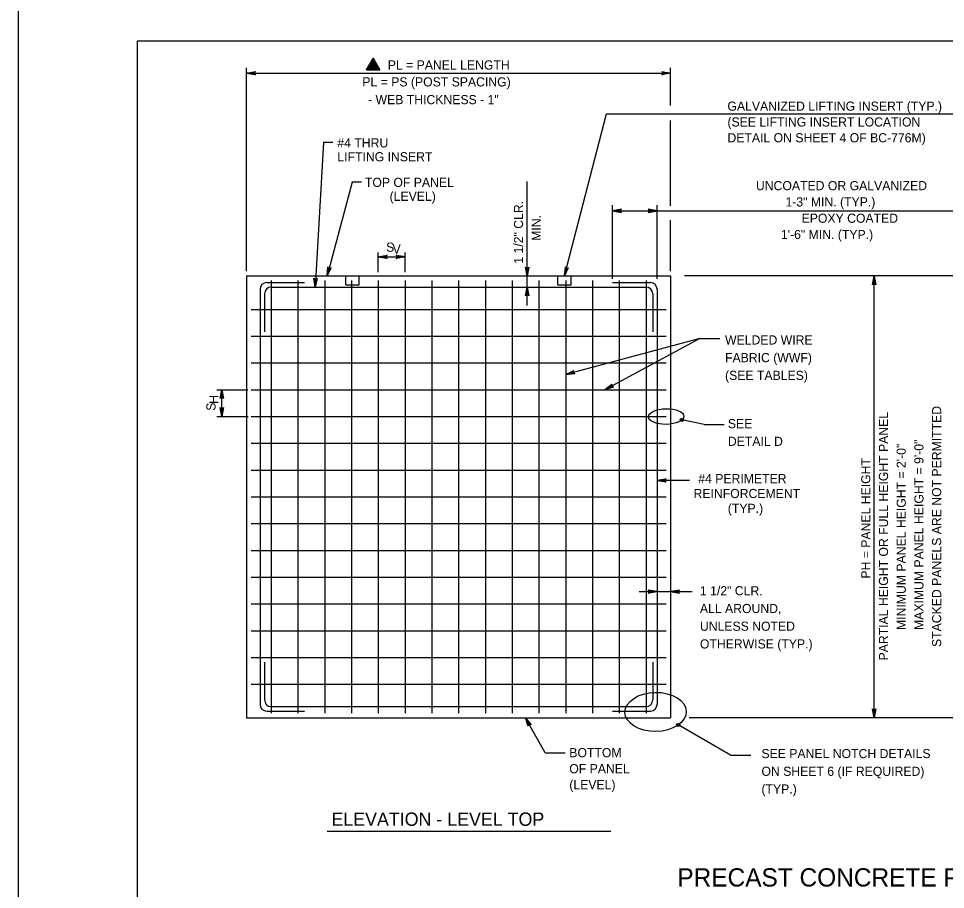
# Model space of a CAD drawing. Extents: x 3761 to 5458, y -616 to 1166.
# Drawn here: x 3761.3 to 4072.9, y -322.5 to -29.8 of the extents above; entities that cross this region are included whole.
import ezdxf

# ---------------------------------------------------------------- set-up
doc = ezdxf.new("R2010")
doc.units = 0
for name, color, linetype in [('1', 7, 'Continuous'), ('2', 7, 'Continuous'), ('PLT-BNDY', 7, 'Continuous')]:
    doc.layers.add(name, color=color, linetype=linetype)

msp = doc.modelspace()

# ---------------------------------------------------------------- linework, layer by layer
at = {"layer": '1'}
for p, q in [((3838.02, -114.74), (3838.02, -46.32)), ((3880.52, -45.74), (3880.52, -45.74)), ((3980.52, -59.07), (3980.52, -46.32)), ((3838.02, -48.22), (3980.52, -48.22)), ((3944.89, -116.32), (3958.96, -61.84)), ((3958.96, -61.84), (4133.46, -61.84)), ((3980.52, -92.71), (3980.52, -64.09)), ((3863.87, -71.45), (3861.01, -120.07)), ((3867.01, -71.45), (3863.87, -71.45)), ((3873.53, -84.81), (3865.1, -116.32)), ((3876.67, -84.81), (3873.53, -84.81)), ((3932.35, -126.29), (3932.35, -84.55)), ((3961.02, -117.3), (3961.02, -92.48)), ((3976.02, -117.3), (3976.02, -92.48)), ((3961.02, -94.44), (4107.86, -94.44)), ((3980.52, -114.74), (3980.52, -97.6)), ((3882.27, -115.01), (3882.27, -108.43)), ((3891.27, -115.01), (3891.27, -108.43)), ((3882.27, -109.9), (3891.27, -109.9)), ((3838.02, -116.32), (3838.02, -264.82)), ((3838.02, -116.32), (3980.52, -116.32)), ((3846.27, -117.82), (3846.27, -263.33)), ((3855.27, -117.82), (3855.27, -263.33)), ((3864.27, -117.82), (3864.27, -263.33)), ((3871.39, -119.32), (3871.39, -116.32)), ((3873.27, -117.82), (3873.27, -263.33)), ((3875.89, -119.32), (3875.89, -116.32)), ((3882.27, -117.82), (3882.27, -263.33)), ((3891.27, -117.82), (3891.27, -263.33)), ((3900.27, -117.82), (3900.27, -263.33)), ((3909.27, -117.82), (3909.27, -263.33)), ((3918.27, -117.82), (3918.27, -263.33)), ((3927.27, -117.82), (3927.27, -263.33)), ((3936.27, -117.82), (3936.27, -263.33)), ((3942.64, -119.32), (3942.64, -116.32)), ((3945.27, -117.82), (3945.27, -263.33)), ((3947.14, -119.32), (3947.14, -116.32)), ((3954.27, -117.82), (3954.27, -263.33)), ((3963.27, -117.82), (3963.27, -263.33)), ((3972.27, -117.82), (3972.27, -263.33)), ((3980.52, -116.32), (3980.52, -264.82)), ((4112.25, -116.32), (3985.19, -116.32)), ((4048.91, -264.82), (4048.91, -116.32)), ((3842.52, -120.82), (3842.52, -260.32)), ((3844.77, -118.57), (3857.52, -118.57)), ((3846.27, -120.07), (3972.27, -120.07)), ((3871.39, -119.32), (3875.89, -119.32)), ((3942.64, -119.32), (3947.14, -119.32)), ((3961.02, -118.57), (3973.77, -118.57)), ((3976.02, -120.82), (3976.02, -260.32)), ((3844.02, -122.32), (3844.02, -135.07)), ((3974.52, -122.32), (3974.52, -135.07)), ((3839.52, -127.57), (3979.02, -127.57)), ((3839.52, -136.57), (3979.02, -136.57)), ((3990.33, -137.36), (3945.27, -149.41)), ((3990.33, -137.36), (3958.44, -154.57)), ((3990.33, -137.36), (3997.07, -137.36)), ((3839.52, -145.57), (3979.02, -145.57)), ((3827.99, -154.57), (3838.42, -154.57)), ((3829.63, -163.57), (3829.63, -154.57)), ((3839.52, -154.57), (3979.02, -154.57)), ((3827.99, -163.57), (3838.51, -163.57)), ((3839.52, -163.57), (3979.02, -163.57)), ((3991.79, -166.23), (3984.3, -164.72)), ((3991.79, -166.23), (3998.52, -166.23)), ((3839.52, -172.57), (3979.02, -172.57)), ((3839.52, -181.57), (3979.02, -181.57)), ((3986.87, -185.05), (3976.02, -185.05)), ((3839.52, -190.57), (3979.02, -190.57)), ((3839.52, -199.57), (3979.02, -199.57)), ((3839.52, -208.57), (3979.02, -208.57)), ((3839.52, -217.57), (3979.02, -217.57)), ((3970, -222.43), (3987.73, -222.43)), ((3839.52, -226.57), (3979.02, -226.57)), ((3839.52, -235.57), (3979.02, -235.57)), ((3839.52, -244.57), (3979.02, -244.57)), ((3844.02, -246.08), (3844.02, -258.83)), ((3974.52, -246.08), (3974.52, -258.83)), ((3839.52, -253.57), (3979.02, -253.57)), ((3846.27, -261.08), (3972.27, -261.08)), ((3838.02, -264.82), (3980.52, -264.82)), ((3844.77, -262.57), (3857.52, -262.57)), ((3938.33, -276.61), (3931.72, -264.82)), ((3961.02, -262.57), (3973.77, -262.57)), ((4110.98, -264.82), (3986.76, -264.82)), ((4000.72, -277.4), (3983.09, -267.24)), ((3938.33, -276.61), (3945.06, -276.61)), ((4000.72, -277.4), (4007.45, -277.4)), ((3865.09, -302.99), (3960.49, -302.99))]:
    msp.add_line(p, q, dxfattribs=at)
for points in [[(3878.29, -47.03), (3882.75, -47.03), (3880.52, -43.17), (3878.29, -47.03)], [(3878.29, -47.03), (3880.52, -43.17), (3882.75, -47.03), (3878.29, -47.03), (3880.51, -43.28), (3882.68, -46.98), (3878.37, -46.99), (3880.52, -43.39), (3882.59, -46.92), (3878.48, -46.94), (3880.52, -43.51), (3882.49, -46.85), (3878.57, -46.88), (3880.52, -43.62), (3882.39, -46.8), (3878.68, -46.81), (3880.52, -43.76), (3882.28, -46.75), (3878.8, -46.75), (3880.52, -43.9), (3882.18, -46.68), (3878.9, -46.69), (3880.51, -44.03), (3882.07, -46.61), (3879.01, -46.62), (3880.51, -44.16), (3881.95, -46.54), (3879.12, -46.56), (3880.53, -44.28), (3881.81, -46.48), (3879.23, -46.5), (3880.53, -44.41), (3881.68, -46.4), (3879.35, -46.44), (3880.53, -44.56), (3881.56, -46.32), (3879.47, -46.37), (3880.52, -44.69), (3881.44, -46.25), (3879.6, -46.3), (3880.53, -44.82), (3881.33, -46.19), (3879.73, -46.24), (3880.52, -44.97), (3881.2, -46.12), (3879.87, -46.17), (3880.52, -45.1), (3881.06, -46.04), (3879.98, -46.11), (3880.52, -45.23), (3880.94, -45.97), (3880.1, -46.05), (3880.52, -45.36), (3880.83, -45.93), (3880.21, -45.99), (3880.52, -45.48), (3880.74, -45.87), (3880.31, -45.93), (3880.52, -45.61), (3880.65, -45.82), (3880.43, -45.85), (3880.52, -45.75), (3882.74, -47.02), (3880.52, -45.75), (3880.52, -43.19), (3880.52, -45.76), (3878.29, -47.02)], [(3838.02, -48.22), (3841, -47.66), (3840.77, -47.82), (3840.65, -48.02), (3840.62, -48.22), (3840.65, -48.42), (3840.77, -48.62), (3841, -48.78), (3838.02, -48.22), (3840.77, -48.62), (3840.65, -48.42), (3838.02, -48.22), (3840.62, -48.22), (3840.65, -48.02), (3838.02, -48.22), (3840.77, -47.82)], [(3980.52, -48.22), (3977.54, -48.78), (3977.77, -48.62), (3977.88, -48.42), (3977.92, -48.22), (3977.88, -48.02), (3977.77, -47.82), (3977.54, -47.66), (3980.52, -48.22), (3977.77, -47.82), (3977.88, -48.02), (3980.52, -48.22), (3977.92, -48.22), (3977.88, -48.42), (3980.52, -48.22), (3977.77, -48.62)], [(3961.02, -94.44), (3964, -95), (3963.89, -94.92), (3963.77, -94.84), (3963.71, -94.74), (3963.65, -94.64), (3963.64, -94.54), (3963.62, -94.44), (3963.64, -94.34), (3963.65, -94.24), (3963.71, -94.14), (3963.77, -94.04), (3963.89, -93.96), (3964, -93.88), (3961.02, -94.44), (3963.89, -93.96), (3963.77, -94.04), (3961.02, -94.44), (3963.71, -94.14), (3963.65, -94.24), (3961.02, -94.44), (3963.64, -94.34), (3963.62, -94.44), (3961.02, -94.44), (3963.64, -94.54), (3963.65, -94.64), (3961.02, -94.44), (3963.71, -94.74), (3963.77, -94.84), (3961.02, -94.44), (3963.89, -94.92)], [(3976.02, -94.44), (3973.04, -93.88), (3973.15, -93.96), (3973.27, -94.04), (3973.32, -94.14), (3973.38, -94.24), (3973.4, -94.34), (3973.42, -94.44), (3973.4, -94.54), (3973.38, -94.64), (3973.32, -94.74), (3973.27, -94.84), (3973.15, -94.92), (3973.04, -95), (3976.02, -94.44), (3973.15, -94.92), (3973.27, -94.84), (3976.02, -94.44), (3973.32, -94.74), (3973.38, -94.64), (3976.02, -94.44), (3973.4, -94.54), (3973.42, -94.44), (3976.02, -94.44), (3973.4, -94.34), (3973.38, -94.24), (3976.02, -94.44), (3973.32, -94.14), (3973.27, -94.04), (3976.02, -94.44), (3973.15, -93.96)], [(3882.27, -109.9), (3885.25, -109.34), (3885.02, -109.5), (3884.9, -109.7), (3884.87, -109.9), (3884.9, -110.1), (3885.02, -110.3), (3885.25, -110.46), (3882.27, -109.9), (3885.02, -110.3), (3884.9, -110.1), (3882.27, -109.9), (3884.87, -109.9), (3884.9, -109.7), (3882.27, -109.9), (3885.02, -109.5)], [(3891.27, -109.9), (3888.28, -110.46), (3888.51, -110.3), (3888.63, -110.1), (3888.67, -109.9), (3888.63, -109.7), (3888.51, -109.5), (3888.28, -109.34), (3891.27, -109.9), (3888.51, -109.5), (3888.63, -109.7), (3891.27, -109.9), (3888.67, -109.9), (3888.63, -110.1), (3891.27, -109.9), (3888.51, -110.3)], [(3865.1, -116.32), (3865.33, -113.3), (3865.38, -113.43), (3865.43, -113.56), (3865.51, -113.65), (3865.59, -113.73), (3865.68, -113.77), (3865.77, -113.81), (3865.88, -113.82), (3865.98, -113.83), (3866.09, -113.8), (3866.2, -113.77), (3866.31, -113.68), (3866.41, -113.59), (3865.1, -116.32), (3866.31, -113.68), (3866.2, -113.77), (3865.1, -116.32), (3866.09, -113.8), (3865.98, -113.83), (3865.1, -116.32), (3865.88, -113.82), (3865.77, -113.81), (3865.1, -116.32), (3865.68, -113.77), (3865.59, -113.73), (3865.1, -116.32), (3865.51, -113.65), (3865.43, -113.56), (3865.1, -116.32), (3865.38, -113.43)], [(3932.35, -116.32), (3931.79, -113.34), (3931.95, -113.57), (3932.15, -113.69), (3932.35, -113.72), (3932.55, -113.69), (3932.75, -113.57), (3932.91, -113.34), (3932.35, -116.32), (3932.75, -113.57), (3932.55, -113.69), (3932.35, -116.32), (3932.35, -113.72), (3932.15, -113.69), (3932.35, -116.32), (3931.95, -113.57)], [(3944.89, -116.32), (3946.26, -113.62), (3946.15, -113.7), (3946.04, -113.79), (3945.93, -113.82), (3945.82, -113.85), (3945.72, -113.84), (3945.62, -113.83), (3945.53, -113.78), (3945.44, -113.74), (3945.36, -113.65), (3945.28, -113.57), (3945.23, -113.44), (3945.19, -113.3), (3944.89, -116.32), (3945.23, -113.44), (3945.28, -113.57), (3944.89, -116.32), (3945.36, -113.65), (3945.44, -113.74), (3944.89, -116.32), (3945.53, -113.78), (3945.62, -113.83), (3944.89, -116.32), (3945.72, -113.84), (3945.82, -113.85), (3944.89, -116.32), (3945.93, -113.82), (3946.04, -113.79), (3944.89, -116.32), (3946.15, -113.7)], [(3861.01, -120.07), (3860.63, -117.06), (3860.78, -117.3), (3860.97, -117.43), (3861.17, -117.48), (3861.37, -117.46), (3861.57, -117.35), (3861.75, -117.13), (3861.01, -120.07), (3861.57, -117.35), (3861.37, -117.46), (3861.01, -120.07), (3861.17, -117.48), (3860.97, -117.43), (3861.01, -120.07), (3860.78, -117.3)], [(4048.91, -116.32), (4049.47, -119.31), (4049.39, -119.19), (4049.31, -119.08), (4049.21, -119.02), (4049.11, -118.96), (4049.01, -118.94), (4048.91, -118.92), (4048.81, -118.94), (4048.71, -118.96), (4048.61, -119.02), (4048.51, -119.08), (4048.43, -119.19), (4048.35, -119.31), (4048.91, -116.32), (4048.43, -119.19), (4048.51, -119.08), (4048.91, -116.32), (4048.61, -119.02), (4048.71, -118.96), (4048.91, -116.32), (4048.81, -118.94), (4048.91, -118.92), (4048.91, -116.32), (4049.01, -118.94), (4049.11, -118.96), (4048.91, -116.32), (4049.21, -119.02), (4049.31, -119.08), (4048.91, -116.32), (4049.39, -119.19)], [(3932.35, -120.07), (3932.91, -123.06), (3932.75, -122.83), (3932.55, -122.71), (3932.35, -122.67), (3932.15, -122.71), (3931.95, -122.83), (3931.79, -123.06), (3932.35, -120.07), (3931.95, -122.83), (3932.15, -122.71), (3932.35, -120.07), (3932.35, -122.67), (3932.55, -122.71), (3932.35, -120.07), (3932.75, -122.83)], [(3945.27, -149.41), (3948, -148.1), (3947.91, -148.2), (3947.82, -148.31), (3947.79, -148.42), (3947.76, -148.54), (3947.77, -148.64), (3947.78, -148.74), (3947.82, -148.83), (3947.86, -148.92), (3947.95, -149), (3948.03, -149.08), (3948.16, -149.13), (3948.29, -149.18), (3945.27, -149.41), (3948.16, -149.13), (3948.03, -149.08), (3945.27, -149.41), (3947.95, -149), (3947.86, -148.92), (3945.27, -149.41), (3947.82, -148.83), (3947.78, -148.74), (3945.27, -149.41), (3947.77, -148.64), (3947.76, -148.54), (3945.27, -149.41), (3947.79, -148.42), (3947.82, -148.31), (3945.27, -149.41), (3947.91, -148.2)], [(3958.44, -154.57), (3960.8, -152.67), (3960.73, -152.79), (3960.67, -152.92), (3960.67, -153.03), (3960.66, -153.15), (3960.69, -153.24), (3960.73, -153.34), (3960.79, -153.42), (3960.85, -153.5), (3960.95, -153.56), (3961.05, -153.62), (3961.19, -153.63), (3961.33, -153.65), (3958.44, -154.57), (3961.19, -153.63), (3961.05, -153.62), (3958.44, -154.57), (3960.95, -153.56), (3960.85, -153.5), (3958.44, -154.57), (3960.79, -153.42), (3960.73, -153.34), (3958.44, -154.57), (3960.69, -153.24), (3960.66, -153.15), (3958.44, -154.57), (3960.67, -153.03), (3960.67, -152.92), (3958.44, -154.57), (3960.73, -152.79)], [(3829.63, -154.57), (3830.19, -157.56), (3830.03, -157.33), (3829.83, -157.21), (3829.63, -157.17), (3829.43, -157.21), (3829.23, -157.33), (3829.07, -157.56), (3829.63, -154.57), (3829.23, -157.33), (3829.43, -157.21), (3829.63, -154.57), (3829.63, -157.17), (3829.83, -157.21), (3829.63, -154.57), (3830.03, -157.33)], [(3829.63, -163.57), (3829.07, -160.59), (3829.23, -160.82), (3829.43, -160.94), (3829.63, -160.97), (3829.83, -160.94), (3830.03, -160.82), (3830.19, -160.59), (3829.63, -163.57), (3830.03, -160.82), (3829.83, -160.94), (3829.63, -163.57), (3829.63, -160.97), (3829.43, -160.94), (3829.63, -163.57), (3829.23, -160.82)], [(3829.63, -163.57), (3829.07, -160.59), (3829.23, -160.82), (3829.43, -160.94), (3829.63, -160.97), (3829.83, -160.94), (3830.03, -160.82), (3830.19, -160.59), (3829.63, -163.57), (3830.03, -160.82), (3829.83, -160.94), (3829.63, -163.57), (3829.63, -160.97), (3829.43, -160.94), (3829.63, -163.57), (3829.23, -160.82)], [(3976.02, -185.05), (3979, -184.49), (3978.89, -184.57), (3978.77, -184.65), (3978.71, -184.75), (3978.65, -184.85), (3978.64, -184.95), (3978.62, -185.05), (3978.64, -185.15), (3978.65, -185.25), (3978.71, -185.35), (3978.77, -185.45), (3978.89, -185.53), (3979, -185.61), (3976.02, -185.05), (3978.89, -185.53), (3978.77, -185.45), (3976.02, -185.05), (3978.71, -185.35), (3978.65, -185.25), (3976.02, -185.05), (3978.64, -185.15), (3978.62, -185.05), (3976.02, -185.05), (3978.64, -184.95), (3978.65, -184.85), (3976.02, -185.05), (3978.71, -184.75), (3978.77, -184.65), (3976.02, -185.05), (3978.89, -184.57)], [(3976.02, -222.43), (3973.04, -222.99), (3973.15, -222.91), (3973.27, -222.83), (3973.32, -222.73), (3973.38, -222.63), (3973.4, -222.53), (3973.42, -222.43), (3973.4, -222.33), (3973.38, -222.23), (3973.32, -222.13), (3973.27, -222.03), (3973.15, -221.95), (3973.04, -221.87), (3976.02, -222.43), (3973.15, -221.95), (3973.27, -222.03), (3976.02, -222.43), (3973.32, -222.13), (3973.38, -222.23), (3976.02, -222.43), (3973.4, -222.33), (3973.42, -222.43), (3976.02, -222.43), (3973.4, -222.53), (3973.38, -222.63), (3976.02, -222.43), (3973.32, -222.73), (3973.27, -222.83), (3976.02, -222.43), (3973.15, -222.91)], [(3980.52, -222.43), (3983.5, -221.87), (3983.39, -221.95), (3983.27, -222.03), (3983.21, -222.13), (3983.15, -222.23), (3983.14, -222.33), (3983.12, -222.43), (3983.14, -222.53), (3983.15, -222.63), (3983.21, -222.73), (3983.27, -222.83), (3983.39, -222.91), (3983.5, -222.99), (3980.52, -222.43), (3983.39, -222.91), (3983.27, -222.83), (3980.52, -222.43), (3983.21, -222.73), (3983.15, -222.63), (3980.52, -222.43), (3983.14, -222.53), (3983.12, -222.43), (3980.52, -222.43), (3983.14, -222.33), (3983.15, -222.23), (3980.52, -222.43), (3983.21, -222.13), (3983.27, -222.03), (3980.52, -222.43), (3983.39, -221.95)], [(3931.72, -264.82), (3933.67, -267.15), (3933.41, -267.03), (3933.18, -267.02), (3932.99, -267.09), (3932.83, -267.22), (3932.72, -267.42), (3932.69, -267.7), (3931.72, -264.82), (3932.72, -267.42), (3932.83, -267.22), (3931.72, -264.82), (3932.99, -267.09), (3933.18, -267.02), (3931.72, -264.82), (3933.41, -267.03)], [(4048.91, -264.82), (4048.35, -261.84), (4048.43, -261.96), (4048.51, -262.07), (4048.61, -262.13), (4048.71, -262.19), (4048.81, -262.21), (4048.91, -262.22), (4049.01, -262.21), (4049.11, -262.19), (4049.21, -262.13), (4049.31, -262.07), (4049.39, -261.96), (4049.47, -261.84), (4048.91, -264.82), (4049.39, -261.96), (4049.31, -262.07), (4048.91, -264.82), (4049.21, -262.13), (4049.11, -262.19), (4048.91, -264.82), (4049.01, -262.21), (4048.91, -262.22), (4048.91, -264.82), (4048.81, -262.21), (4048.71, -262.19), (4048.91, -264.82), (4048.61, -262.13), (4048.51, -262.07), (4048.91, -264.82), (4048.43, -261.96)]]:
    msp.add_lwpolyline(points, dxfattribs=at)
for centre, radius in [((3984.3, -164.72), 0.533), ((3984.3, -164.72), 0.267), ((3983.09, -267.24), 0.533), ((3983.09, -267.24), 0.267)]:
    msp.add_circle(centre, radius, dxfattribs=at)
for centre, start, end in [((3844.77, -120.82), 90, 180), ((3846.27, -122.32), 90, 180), ((3972.27, -122.32), 0, 90), ((3973.77, -120.82), 0, 90), ((3844.77, -260.32), 180, 270), ((3846.27, -258.83), 180, 270), ((3972.27, -258.83), 270, 360), ((3973.77, -260.32), 270, 0)]:
    msp.add_arc(centre, 2.25, start, end, dxfattribs=at)
for centre, major_axis, ratio in [((3979.02, -163.57), (-5.94, -0.09), 0.443512), ((3975.49, -262.86), (-10.3, -0.16), 0.638969)]:
    msp.add_ellipse(centre, major_axis=major_axis, ratio=ratio, dxfattribs=at)
at = {"layer": '2'}
for p, q in [((3801.34, -601.31), (3801.34, -37.31)), ((3801.34, -37.31), (4587.34, -37.31))]:
    msp.add_line(p, q, dxfattribs=at)
at = {"layer": 'PLT-BNDY'}
msp.add_lwpolyline([(3761.34, -22.31), (4602.34, -22.31), (4602.34, -616.31), (3761.34, -616.31)], close=True, dxfattribs=at)

# ---------------------------------------------------------------- texts
at = {"layer": '1'}
for s, height, p in [('PL = PANEL LENGTH', 3.072, (3885.46, -46.95)), ('PL = PS (POST SPACING)', 3.072, (3876.91, -52.63)), ('- WEB THICKNESS - 1"', 3.072, (3878.84, -58.59)), ('GALVANIZED LIFTING INSERT (TYP.)', 3.072, (3999.64, -60.79)), ('(SEE LIFTING INSERT LOCATION', 3.072, (3999.64, -66.1)), ('DETAIL ON SHEET 4 OF BC-776M)', 3.072, (3999.64, -71.41)), ('#4 THRU ', 3.072, (3868.51, -73.12)), ('LIFTING INSERT', 3.0721, (3868.51, -77.8)), ('TOP OF PANEL', 3.072, (3877.77, -86.41)), ('UNCOATED OR GALVANIZED', 3.072, (4009.21, -87.51)), ('(LEVEL)', 3.072, (3886.08, -91.08)), ('1-3" MIN. (TYP.)', 3.072, (4019.14, -92.98)), ('EPOXY COATED', 3.072, (4024.57, -98.46)), ('1\'-6" MIN. (TYP.)', 3.072, (4017.61, -103.93)), ('S', 3.07, (3884.89, -108.19)), ('V', 3.07, (3887.07, -108.81)), ('WELDED WIRE', 3.072, (3998.83, -139.37)), ('FABRIC (WWF)', 3.072, (3998.83, -145.32)), ('(SEE TABLES)', 3.072, (3998.83, -151.27)), ('SEE', 3.072, (3999.78, -167.49)), ('DETAIL D', 3.072, (3999.78, -173.44)), ('#4 PERIMETER', 3.072, (3989.83, -185.99)), ('REINFORCEMENT', 3.072, (3988.24, -190.98)), ('(TYP.)', 3.072, (3999.76, -195.97)), ('1 1/2" CLR.', 3.072, (3990.38, -223.67)), ('ALL AROUND,', 3.072, (3990.38, -229.63)), ('UNLESS NOTED', 3.072, (3990.38, -235.58)), ('OTHERWISE (TYP.)', 3.072, (3990.38, -241.53)), ('BOTTOM', 3.072, (3946.48, -278.08)), ('SEE PANEL NOTCH DETAILS', 3.072, (4011.07, -278.39)), ('OF PANEL', 3.072, (3946.48, -283.46)), ('ON SHEET 6 (IF REQUIRED)', 3.072, (4011.07, -284.35)), ('(LEVEL)', 3.072, (3946.48, -288.84)), ('(TYP.)', 3.072, (4011.07, -290.3)), ('ELEVATION - LEVEL TOP', 4.4774, (3866.52, -301.14)), ('PRECAST CONCRETE PANEL', 6.144, (3982.78, -321.54))]:
    msp.add_text(s, height=height, dxfattribs=at).set_placement(p)
for s, height, p in [('1 1/2" CLR.', 3.072, (3930.94, -112.2)), ('MIN.', 3.072, (3936.89, -104.52)), ('H', 3.07, (3828.52, -159.31)), ('S', 3.07, (3827.56, -161.64)), ('STACKED PANELS ARE NOT PERMITTED', 3.072, (4071.49, -241.04)), ('PARTIAL HEIGHT OR FULL HEIGHT PANEL', 3.072, (4053.63, -245.56)), ('MINIMUM PANEL HEIGHT = 2\'-0"', 3.072, (4059.58, -235.32)), ('MAXIMUM PANEL HEIGHT = 9\'-0"', 3.072, (4065.53, -235.32)), ('PH = PANEL HEIGHT', 3.072, (4047.68, -218.06))]:
    msp.add_text(s, height=height, rotation=90, dxfattribs=at).set_placement(p)

doc.saveas('drawing.dxf')
